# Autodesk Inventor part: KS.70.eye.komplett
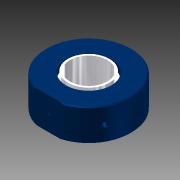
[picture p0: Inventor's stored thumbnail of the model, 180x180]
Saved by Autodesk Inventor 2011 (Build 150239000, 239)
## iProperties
Created: 2010-11
Part Number: KS.70.eye.komplett
Document SubType Name: Modeling
Designer: tribel
Density: 1 g/cm^3
Author: tribel
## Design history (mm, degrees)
derived "KS70eye.iam"
body "Solid1"
node "Lagerhus70.ipt:1"
node "Kule70HO.ipt:1"
sketch "Smørenippel.ipt:1"
